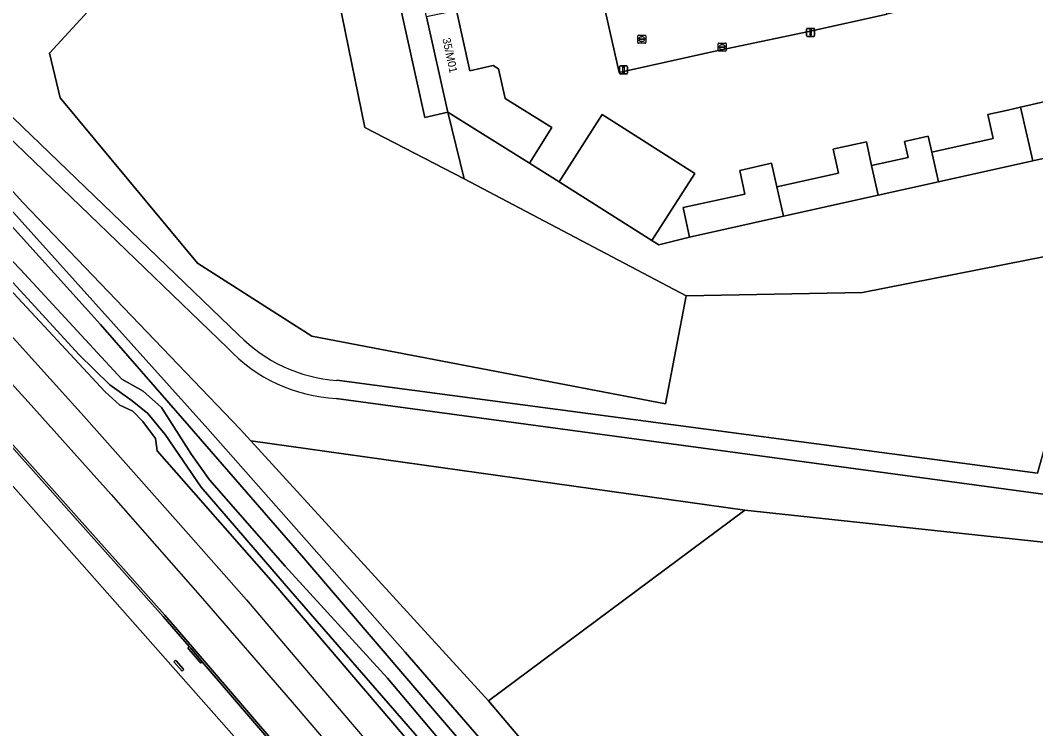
# Model space of a CAD drawing. Extents: x 164494 to 166241, y 382475 to 384495.
# Drawn here: x 164592.4 to 164719.3, y 383290.3 to 383378.9 of the extents above; entities that cross this region are included whole.
import ezdxf

# ---------------------------------------------------------------- set-up
doc = ezdxf.new("R2010")
doc.units = 0
for name, color, linetype in [('IMGEO_Erf', 7, 'Continuous'), ('IMGEO_Geluidsscherm', 7, 'Continuous'), ('IMGEO_Grasland_agrarisch', 7, 'Continuous'), ('IMGEO_Grasland_overig', 7, 'Continuous'), ('IMGEO_Greppel_droge_sloot', 7, 'Continuous'), ('IMGEO_Groenvoorziening', 7, 'Continuous'), ('IMGEO_Hek', 7, 'Continuous'), ('IMGEO_Kolk', 7, 'Continuous'), ('IMGEO_Lichtmast', 7, 'Continuous'), ('IMGEO_Loofbos', 7, 'Continuous'), ('IMGEO_Muur', 7, 'Continuous'), ('IMGEO_Pand', 7, 'Continuous'), ('IMGEO_Pand_nummerreeks', 7, 'Continuous'), ('IMGEO_Rijbaan_lokaal_open', 7, 'Continuous'), ('IMGEO_Rioolput', 7, 'Continuous'), ('IMGEO_Spoor', 7, 'Continuous'), ('IMGEO_Spoorbaan_halfverhard', 7, 'Continuous'), ('IMGEO_Terreindeel_gesloten', 7, 'Continuous'), ('IMGEO_Voetpad_halfverhard', 7, 'Continuous')]:
    doc.layers.add(name, color=color, linetype=linetype)

msp = doc.modelspace()

# ---------------------------------------------------------------- linework, layer by layer
at = {"layer": 'IMGEO_Erf'}
for points in [[(164712.6, 383443.85), (164712.61, 383443.79), (164712.94, 383443.85), (164718.11, 383420.69), (164718.02, 383420.67), (164720.68, 383408.76), (164723.27, 383397.21), (164725.99, 383385.33), (164714.06, 383382.76), (164704.14, 383380.45), (164702.42, 383380.05), (164700.75, 383379.68), (164690.96, 383377.5), (164679.05, 383374.99), (164667.26, 383372.36), (164664.65, 383384.06), (164662.09, 383395.82)], [(164646.95, 383380.15), (164648.59, 383372.6), (164651.54, 383373.24), (164652.2, 383372.82), (164653, 383369.13), (164658.84, 383365.48), (164656.07, 383361.04), (164659.78, 383358.72), (164665.15, 383367.11), (164676.72, 383359.76), (164671.36, 383351.36), (164672.21, 383350.82), (164676.05, 383351.79), (164675.25, 383355.5), (164682.98, 383357.17), (164682.34, 383360.14), (164686.31, 383361.03), (164686.96, 383358.08), (164694.67, 383359.8), (164694, 383362.8), (164694.14, 383362.83), (164698.16, 383363.72), (164698.82, 383360.74), (164703.39, 383361.76), (164702.94, 383363.74), (164705.87, 383364.41), (164706.33, 383362.41), (164714, 383364.11), (164713.34, 383367.12), (164715.83, 383367.68), (164717.41, 383368.04), (164721.44, 383368.96)]]:
    msp.add_lwpolyline(points, dxfattribs=at)
at = {"layer": 'IMGEO_Geluidsscherm'}
for points in [[(164630.07, 383281.29), (164615.17, 383298.69), (164614.96, 383298.93), (164613.72, 383300.37), (164613.54, 383300.58), (164610.29, 383304.33), (164587.13, 383330.28), (164574.53, 383344.16), (164566.74, 383352.48), (164549.76, 383370.16), (164548.93, 383371.03)], [(164549.11, 383371.2), (164549.64, 383370.65), (164566.92, 383352.66), (164574.72, 383344.33), (164587.32, 383330.45), (164610.48, 383304.5), (164613.91, 383300.53), (164615.15, 383299.09), (164630.26, 383281.45)]]:
    msp.add_lwpolyline(points, dxfattribs=at)
at = {"layer": 'IMGEO_Grasland_agrarisch'}
msp.add_lwpolyline([(164717.65, 383214.93), (164719.87, 383217.06), (164726.2, 383223.12), (164759.77, 383255.42), (164799.31, 383293.78), (164769.99, 383308.3), (164682.99, 383317.62), (164650.95, 383293.8)], close=True, dxfattribs=at)
at = {"layer": 'IMGEO_Grasland_overig'}
for points in [[(164648.35, 383284.72), (164638.3, 383296.63), (164625.54, 383310.63), (164616.08, 383321.42), (164613.81, 383324.61), (164610.08, 383330.46), (164607.77, 383332.52), (164605.12, 383334.04), (164592.43, 383347.75), (164567.76, 383373.46)], [(164567.76, 383373.46), (164592.43, 383347.75), (164605.12, 383334.04), (164607.77, 383332.52), (164610.08, 383330.46), (164613.81, 383324.61), (164616.08, 383321.42), (164625.54, 383310.63), (164638.3, 383296.63), (164648.35, 383284.72)], [(164569.79, 383368.19), (164603.03, 383332.42), (164604.85, 383330.79), (164606.47, 383330.01), (164607.75, 383328.71), (164609.3, 383326.62), (164609.53, 383325.06), (164624.36, 383308.16), (164646.76, 383281.93)], [(164573.23, 383366.01), (164599.73, 383337.1), (164603.63, 383333.3), (164606.4, 383331.31), (164608.36, 383329.72), (164610.54, 383327.1), (164615.02, 383320.51), (164626.21, 383307.54), (164647.55, 383282.94)], [(164647.55, 383282.94), (164626.21, 383307.54), (164615.02, 383320.51), (164610.54, 383327.1), (164608.36, 383329.72), (164606.4, 383331.31), (164603.63, 383333.3), (164599.73, 383337.1), (164573.23, 383366.01)], [(164654.34, 383280.65), (164627.85, 383311.62), (164612.71, 383329.12), (164602.43, 383340.85), (164585.53, 383359.56)]]:
    msp.add_lwpolyline(points, dxfattribs=at)
at = {"layer": 'IMGEO_Greppel_droge_sloot'}
msp.add_lwpolyline([(164719.59, 383207.25), (164717.07, 383210.84), (164695.9, 383235.58), (164668.17, 383267.71), (164650.27, 383288.61), (164640.51, 383299.89), (164615.87, 383327.81), (164587.45, 383359.42), (164569.83, 383378.65), (164569.16, 383378.04), (164569.02, 383377.8), (164569.2, 383377.18), (164573.97, 383371.95), (164585.53, 383359.56), (164602.43, 383340.85), (164612.71, 383329.12), (164627.85, 383311.62), (164654.34, 383280.65), (164673.17, 383257.81), (164689.1, 383238.16), (164711.71, 383211.78), (164717.14, 383205.62), (164718.96, 383203.68), (164725.76, 383197.02)], dxfattribs=at)
at = {"layer": 'IMGEO_Groenvoorziening'}
for points in [[(164729.61, 383351.14), (164697.66, 383344.85), (164675.64, 383344.43), (164673.05, 383330.95), (164628.84, 383339.41), (164614.57, 383348.52), (164597.4, 383369.21), (164596.05, 383374.78), (164608.98, 383388.87), (164629.72, 383393.71), (164623.04, 383426.49)], [(164618.37, 383337.91), (164576.81, 383377.91), (164569.8, 383384.91), (164551.1, 383402.1), (164592.72, 383356.14), (164619.91, 383327.76), (164621.22, 383326.32), (164682.99, 383317.62), (164769.99, 383308.3)], [(164717.65, 383214.93), (164650.95, 383293.8), (164621.22, 383326.32), (164619.91, 383327.76), (164592.72, 383356.14), (164551.1, 383402.1)], [(164572.82, 383396.91), (164570.46, 383387.39), (164579.08, 383378.67), (164619.75, 383339.53)], [(164630.07, 383281.29), (164615.17, 383298.69), (164614.98, 383298.52), (164614.77, 383298.77), (164613.53, 383300.21), (164613.35, 383300.42), (164613.54, 383300.58), (164610.29, 383304.33), (164587.13, 383330.28), (164574.53, 383344.16), (164566.74, 383352.48), (164549.76, 383370.16), (164548.78, 383369.22), (164555.12, 383361.79), (164564.15, 383351.56), (164566.35, 383351.22), (164566.12, 383349.33), (164664.5, 383237.97)], [(164730.37, 383363.86), (164718.95, 383361.32), (164707.17, 383358.7), (164699.64, 383357.03), (164687.79, 383354.39), (164676.05, 383351.79), (164672.21, 383350.82), (164671.36, 383351.36), (164659.78, 383358.72), (164656.07, 383361.04), (164645.86, 383367.42), (164647.88, 383359.09), (164675.64, 383344.43), (164697.66, 383344.85), (164729.61, 383351.14)], [(164587.45, 383359.42), (164615.87, 383327.81), (164640.51, 383299.89), (164650.27, 383288.61)], [(164631.97, 383333.88), (164719.54, 383322.28), (164721.02, 383327.49), (164724.34, 383335.2), (164729.41, 383346.58)], [(164777.24, 383312.13), (164759.03, 383314.37), (164631.9, 383331.6)]]:
    msp.add_lwpolyline(points, dxfattribs=at)
for points in [[(164675.64, 383344.43), (164647.88, 383359.09), (164635.47, 383365.51), (164629.72, 383393.71), (164608.98, 383388.87), (164596.05, 383374.78), (164597.4, 383369.21), (164614.57, 383348.52), (164628.84, 383339.41), (164673.05, 383330.95)], [(164650.95, 383293.8), (164682.99, 383317.62), (164621.22, 383326.32)], [(164611.61, 383298.67), (164611.81, 383298.86), (164611.88, 383298.79), (164612.78, 383297.78), (164612.85, 383297.7), (164612.64, 383297.52)]]:
    msp.add_lwpolyline(points, close=True, dxfattribs=at)
for centre, radius, start, end in [((164633.3, 383352.78), 18.95, 224.3626, 265.9855), ((164632.97, 383351.59), 20.02, 223.1266, 266.9221)]:
    msp.add_arc(centre, radius, start, end, dxfattribs=at)
at = {"layer": 'IMGEO_Hek'}
for points in [[(164532.13, 383417.14), (164546.47, 383402.54), (164553.05, 383395.84), (164567.11, 383381.49), (164568.81, 383379.76), (164569.83, 383378.65), (164587.45, 383359.42), (164615.87, 383327.81), (164640.51, 383299.89), (164650.27, 383288.61), (164668.17, 383267.71), (164695.9, 383235.58), (164717.07, 383210.84), (164719.59, 383207.25), (164720.92, 383205.36), (164724.31, 383199.68), (164725.76, 383197.02), (164733.06, 383188.3), (164749.68, 383168.56), (164783.15, 383128.36)], [(164647.88, 383359.09), (164645.86, 383367.42)], [(164675.64, 383344.43), (164647.88, 383359.09)], [(164729.61, 383351.14), (164697.66, 383344.85), (164675.64, 383344.43)], [(164650.95, 383293.8), (164682.99, 383317.62)], [(164682.99, 383317.62), (164769.99, 383308.3), (164799.31, 383293.78)], [(164719.87, 383217.06), (164717.65, 383214.93), (164650.95, 383293.8)]]:
    msp.add_lwpolyline(points, dxfattribs=at)
at = {"layer": 'IMGEO_Kolk'}
for p, q in [((164679.65, 383375.13), (164679.65, 383375.98)), ((164679.72, 383376.05), (164680.57, 383376.05)), ((164680.13, 383375.83), (164680.16, 383375.83)), ((164680.65, 383375.98), (164680.65, 383375.13)), ((164680.57, 383375.05), (164679.72, 383375.05)), ((164679.9, 383375.55), (164679.9, 383375.56)), ((164680.34, 383375.51), (164679.94, 383375.51)), ((164679.95, 383375.6), (164680.34, 383375.6)), ((164680.16, 383375.27), (164680.13, 383375.27)), ((164680.39, 383375.56), (164680.39, 383375.55))]:
    msp.add_line(p, q, dxfattribs=at)
for points in [[(164679.65, 383375.13), (164679.65, 383375.98)], [(164679.72, 383376.05), (164680.57, 383376.05)], [(164680.65, 383375.98), (164680.65, 383375.13)], [(164680.57, 383375.05), (164679.72, 383375.05)]]:
    msp.add_lwpolyline(points, dxfattribs=at)
for centre, radius, start, end in [((164679.72, 383375.98), 0.0765, 91.552, 178.448), ((164679.72, 383375.98), 0.0765, 91.552, 178.448), ((164680.57, 383375.98), 0.0765, 1.552, 88.448), ((164680.57, 383375.98), 0.0765, 1.552, 88.448), ((164679.72, 383375.13), 0.0765, 181.552, 268.448), ((164679.72, 383375.13), 0.0765, 181.552, 268.448), ((164679.94, 383375.56), 0.0403, 85.8775, 175.7526), ((164679.94, 383375.55), 0.0366, 178.938, 274.7102), ((164680.35, 383375.56), 0.0386, 1.7309, 96.639), ((164680.35, 383375.55), 0.043, 264.8664, 352.4533), ((164680.57, 383375.13), 0.0765, 271.552, 358.448), ((164680.57, 383375.13), 0.0765, 271.552, 358.448)]:
    msp.add_arc(centre, radius, start, end, dxfattribs=at)
for centre, major_axis, ratio, start_param, end_param in [((164680.13, 383375.55), (-0.387, 0.002), 0.722429, 4.712389, 7.853982), ((164680.16, 383375.55), (-0.39, 0.002), 0.717154, 1.570796, 4.712389)]:
    msp.add_ellipse(centre, major_axis=major_axis, ratio=ratio, start_param=start_param, end_param=end_param, dxfattribs=at)
at = {"layer": 'IMGEO_Lichtmast'}
for p, q in [((164690.7, 383377), (164690.7, 383377.8)), ((164690.7, 383377.8), (164690.7, 383377)), ((164690.8, 383377.9), (164691.59, 383377.9)), ((164691.59, 383377.9), (164690.8, 383377.9)), ((164691.59, 383376.9), (164690.8, 383376.9)), ((164690.8, 383376.9), (164691.59, 383376.9)), ((164691.69, 383377.8), (164691.69, 383377)), ((164691.69, 383377), (164691.69, 383377.8)), ((164667.32, 383372.3), (164667.32, 383373.1)), ((164667.32, 383373.1), (164667.32, 383372.3)), ((164667.42, 383373.2), (164668.21, 383373.2)), ((164668.21, 383373.2), (164667.42, 383373.2)), ((164668.31, 383373.1), (164668.31, 383372.3)), ((164668.31, 383372.3), (164668.31, 383373.1)), ((164668.21, 383372.2), (164667.42, 383372.2)), ((164667.42, 383372.2), (164668.21, 383372.2))]:
    msp.add_line(p, q, dxfattribs=at)
for points in [[(164691.12, 383377.78), (164691.27, 383377.78), (164691.27, 383377.03), (164691.12, 383377.03), (164691.12, 383377.78)], [(164667.74, 383373.08), (164667.89, 383373.08), (164667.89, 383372.33), (164667.74, 383372.33), (164667.74, 383373.08)]]:
    msp.add_lwpolyline(points, dxfattribs=at)
for centre, start, end in [((164690.8, 383377.8), 90, 180), ((164690.8, 383377.8), 90, 180), ((164690.8, 383377), 180, 270), ((164690.8, 383377), 180, 270), ((164691.59, 383377.8), 0, 90), ((164691.59, 383377.8), 360, 90), ((164691.59, 383377), 270, 0), ((164691.59, 383377), 270, 0), ((164667.42, 383373.1), 90, 180), ((164667.42, 383373.1), 90, 180), ((164668.21, 383373.1), 0, 90), ((164668.21, 383373.1), 360, 90), ((164667.42, 383372.3), 180, 270), ((164667.42, 383372.3), 180, 270), ((164668.21, 383372.3), 270, 0), ((164668.21, 383372.3), 270, 0)]:
    msp.add_arc(centre, 0.1, start, end, dxfattribs=at)
at = {"layer": 'IMGEO_Loofbos'}
for points in [[(164629.47, 383427.84), (164623.04, 383426.49), (164629.72, 383393.71), (164635.47, 383365.51), (164647.88, 383359.09), (164645.86, 383367.42), (164643, 383366.76)], [(164638, 383402.61), (164635.36, 383414.47), (164632.76, 383426.09), (164632.24, 383428.43), (164629.47, 383427.84), (164643, 383366.76), (164645.86, 383367.42), (164645.82, 383367.57), (164643.2, 383379.34), (164640.57, 383391.13)]]:
    msp.add_lwpolyline(points, close=True, dxfattribs=at)
at = {"layer": 'IMGEO_Muur'}
msp.add_lwpolyline([(164548.93, 383371.03), (164549.76, 383370.16), (164566.74, 383352.48), (164574.53, 383344.16), (164587.13, 383330.28), (164610.29, 383304.33), (164613.54, 383300.58), (164613.72, 383300.37), (164614.96, 383298.93), (164615.17, 383298.69), (164630.07, 383281.29), (164630.26, 383281.45), (164615.15, 383299.09), (164613.91, 383300.53), (164610.48, 383304.5), (164587.32, 383330.45), (164574.72, 383344.33), (164566.92, 383352.66), (164549.64, 383370.65), (164549.11, 383371.2), (164548.95, 383371.05)], close=True, dxfattribs=at)
at = {"layer": 'IMGEO_Pand'}
for points in [[(164646.95, 383380.15), (164643.2, 383379.34), (164645.82, 383367.57), (164645.86, 383367.42), (164656.07, 383361.04), (164658.84, 383365.48), (164653, 383369.13), (164652.2, 383372.82), (164651.54, 383373.24), (164648.59, 383372.6)], [(164718.95, 383361.32), (164717.41, 383368.04), (164715.83, 383367.68), (164713.34, 383367.12), (164714, 383364.11), (164706.33, 383362.41), (164707.17, 383358.7)], [(164729.55, 383367.57), (164722.13, 383365.92), (164721.44, 383368.96), (164717.41, 383368.04), (164718.95, 383361.32), (164730.37, 383363.86), (164730.27, 383364.31)], [(164676.72, 383359.76), (164665.15, 383367.11), (164659.78, 383358.72), (164671.36, 383351.36)], [(164706.33, 383362.41), (164705.87, 383364.41), (164702.94, 383363.74), (164703.39, 383361.76), (164698.82, 383360.74), (164699.64, 383357.03), (164707.17, 383358.7)], [(164699.64, 383357.03), (164698.82, 383360.74), (164698.16, 383363.72), (164694.14, 383362.83), (164694, 383362.8), (164694.67, 383359.8), (164686.96, 383358.08), (164687.79, 383354.39)], [(164686.96, 383358.08), (164686.31, 383361.03), (164682.34, 383360.14), (164682.98, 383357.17), (164675.25, 383355.5), (164676.05, 383351.79), (164687.79, 383354.39)]]:
    msp.add_lwpolyline(points, close=True, dxfattribs=at)
at = {"layer": 'IMGEO_Rijbaan_lokaal_open'}
msp.add_lwpolyline([(164669.71, 383384.42), (164667.9, 383392.6), (164667.85, 383392.83), (164663.29, 383413.32), (164663.23, 383413.57), (164658.35, 383412.42), (164658.44, 383412.04), (164659.43, 383407.62), (164662.09, 383395.82), (164664.65, 383384.06), (164667.26, 383372.36), (164679.05, 383374.99), (164690.96, 383377.5), (164700.75, 383379.68), (164699.59, 383384.86)], dxfattribs=at)
at = {"layer": 'IMGEO_Rioolput'}
for p, q in [((164669.6, 383376.12), (164669.6, 383376.97)), ((164669.67, 383377.05), (164670.52, 383377.05)), ((164670.6, 383376.97), (164670.6, 383376.12)), ((164670.52, 383376.05), (164669.67, 383376.05)), ((164669.85, 383376.54), (164669.85, 383376.55)), ((164670.29, 383376.5), (164669.89, 383376.5)), ((164669.9, 383376.59), (164670.29, 383376.59)), ((164670.08, 383376.83), (164670.11, 383376.83)), ((164670.11, 383376.27), (164670.08, 383376.27)), ((164670.34, 383376.55), (164670.34, 383376.54))]:
    msp.add_line(p, q, dxfattribs=at)
for points in [[(164669.6, 383376.12), (164669.6, 383376.97)], [(164669.67, 383377.05), (164670.52, 383377.05)], [(164670.6, 383376.97), (164670.6, 383376.12)], [(164670.52, 383376.05), (164669.67, 383376.05)]]:
    msp.add_lwpolyline(points, dxfattribs=at)
for centre, radius, start, end in [((164669.67, 383376.97), 0.0765, 91.552, 178.448), ((164669.67, 383376.97), 0.0765, 91.552, 178.448), ((164670.52, 383376.97), 0.0765, 1.552, 88.448), ((164670.52, 383376.97), 0.0765, 1.552, 88.448), ((164669.67, 383376.12), 0.0765, 181.552, 268.448), ((164669.67, 383376.12), 0.0765, 181.552, 268.448), ((164669.89, 383376.55), 0.0403, 85.8775, 175.7526), ((164669.89, 383376.54), 0.0366, 178.938, 274.7102), ((164670.3, 383376.55), 0.0386, 1.7309, 96.639), ((164670.3, 383376.55), 0.043, 264.8664, 352.4533), ((164670.52, 383376.12), 0.0765, 271.552, 358.448), ((164670.52, 383376.12), 0.0765, 271.552, 358.448)]:
    msp.add_arc(centre, radius, start, end, dxfattribs=at)
for centre, major_axis, ratio, start_param, end_param in [((164670.08, 383376.55), (-0.387, 0.002), 0.722429, 4.712389, 7.853982), ((164670.11, 383376.55), (-0.39, 0.002), 0.717154, 1.570796, 4.712389)]:
    msp.add_ellipse(centre, major_axis=major_axis, ratio=ratio, start_param=start_param, end_param=end_param, dxfattribs=at)
at = {"layer": 'IMGEO_Spoor'}
for points in [[(164497.16, 383435.76), (164505.01, 383428.31), (164523.25, 383410.43), (164538.04, 383395.69), (164557.43, 383375.71), (164570.01, 383362.48), (164585.76, 383345.51), (164600.35, 383329.41), (164613.46, 383314.64), (164620.68, 383306.41), (164626.03, 383300.15), (164652.19, 383269.4), (164681.85, 383233.76), (164715.83, 383193.24), (164785.24, 383110.17), (164816.48, 383072.61), (164890.55, 382984.09), (164958.66, 382902.34), (164967.09, 382892.29)], [(164494.45, 383433), (164503, 383424.89), (164513.86, 383414.22), (164535.42, 383392.64), (164546.22, 383381.6), (164561.18, 383366.01), (164572.19, 383354.32), (164582.17, 383343.51), (164593.42, 383331.17), (164603.76, 383319.61), (164615.18, 383306.6), (164626.39, 383293.63), (164637.88, 383280.18), (164662.08, 383251.56), (164693.34, 383214.26), (164754.17, 383141.12), (164812.5, 383071.43), (164837.86, 383040.96), (164896.06, 382971.37), (164932.4, 382927.69), (164964.12, 382889.8)]]:
    msp.add_lwpolyline(points, dxfattribs=at)
at = {"layer": 'IMGEO_Spoorbaan_halfverhard'}
for points in [[(164646.76, 383281.93), (164624.36, 383308.16), (164609.53, 383325.06), (164609.3, 383326.62), (164607.75, 383328.71), (164606.47, 383330.01), (164604.85, 383330.79), (164603.03, 383332.42), (164569.79, 383368.19)], [(164587.32, 383330.45), (164610.48, 383304.5), (164613.91, 383300.53), (164615.15, 383299.09), (164630.26, 383281.45)]]:
    msp.add_lwpolyline(points, dxfattribs=at)
at = {"layer": 'IMGEO_Terreindeel_gesloten'}
for points in [[(164614.96, 383298.93), (164613.72, 383300.37), (164613.54, 383300.58), (164613.35, 383300.42), (164613.53, 383300.21), (164614.77, 383298.77), (164614.98, 383298.52), (164615.17, 383298.69)], [(164612.78, 383297.78), (164611.88, 383298.79), (164611.81, 383298.86), (164611.61, 383298.67), (164612.64, 383297.52), (164612.85, 383297.7)]]:
    msp.add_lwpolyline(points, close=True, dxfattribs=at)
at = {"layer": 'IMGEO_Voetpad_halfverhard'}
for points in [[(164619.75, 383339.53), (164579.08, 383378.67)], [(164576.81, 383377.91), (164618.37, 383337.91)], [(164729.41, 383346.58), (164724.34, 383335.2), (164721.02, 383327.49), (164719.54, 383322.28), (164631.97, 383333.88)], [(164631.9, 383331.6), (164759.03, 383314.37), (164777.24, 383312.13)]]:
    msp.add_lwpolyline(points, dxfattribs=at)
for centre, radius, start, end in [((164633.3, 383352.78), 18.95, 224.3626, 265.9855), ((164632.97, 383351.59), 20.02, 223.1266, 266.9221)]:
    msp.add_arc(centre, radius, start, end, dxfattribs=at)

# ---------------------------------------------------------------- texts
at = {"layer": 'IMGEO_Pand_nummerreeks'}
msp.add_text('35/M01', height=1, rotation=282.0777, dxfattribs=at).set_placement((164645.17, 383376.6))

doc.saveas('drawing.dxf')
